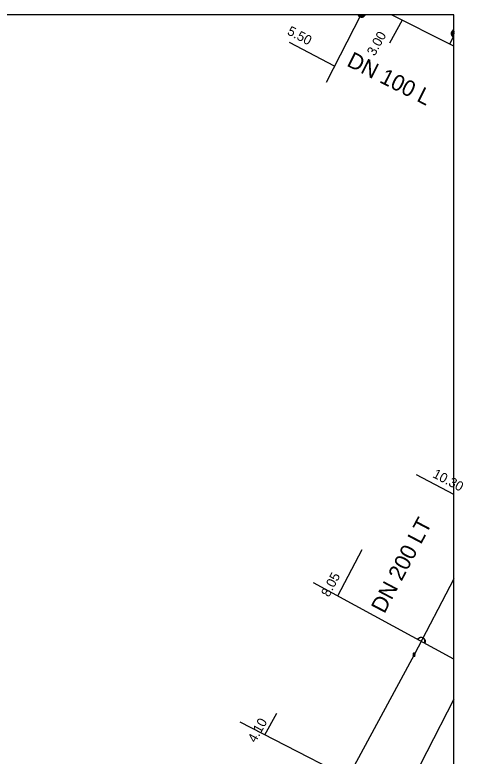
# Model space of a CAD drawing. Extents: x -820257 to -819974, y -1070894 to -1070484.
# Drawn here: x -820030.6 to -819974.5, y -1070577.4 to -1070484.4 of the extents above; entities that cross this region are included whole.
import ezdxf

# ---------------------------------------------------------------- set-up
doc = ezdxf.new("R2010")
doc.units = 0
for name, color, linetype in [('Default', 7, 'Continuous'), ('Lomový bod vodovodu', 7, 'Continuous'), ('Nepropojené křížení vodovodu', 7, 'Continuous'), ('Oměrka vodovodu', 7, 'Continuous'), ('Oměrka-text', 7, 'Continuous'), ('Přípojka vodovodu', 7, 'Continuous'), ('Přípojkový uzávěr', 7, 'Continuous'), ('Roz-řad', 7, 'Continuous'), ('Roz-řad-popis základní', 7, 'Continuous')]:
    doc.layers.add(name, color=color, linetype=linetype)

msp = doc.modelspace()

# ---------------------------------------------------------------- linework, layer by layer
at = {"layer": 'Default'}
msp.add_line((-819975.603, -1070893.932), (-819975.603, -1070484.403), dxfattribs=at)
msp.add_lwpolyline([(-819975.603, -1070484.403), (-820256.81, -1070484.403), (-820256.81, -1070893.932)], dxfattribs=at)
at = {"layer": 'Lomový bod vodovodu'}
for points in [[(-819980.638, -1070564.586), (-819980.7, -1070564.45), (-819980.5, -1070564.45), (-819980.563, -1070564.586)], [(-819980.563, -1070564.714), (-819980.5, -1070564.85), (-819980.7, -1070564.85), (-819980.638, -1070564.714)], [(-819980.578, -1070564.579), (-819980.524, -1070564.463), (-819980.678, -1070564.463), (-819980.623, -1070564.579)], [(-819980.623, -1070564.721), (-819980.678, -1070564.838), (-819980.524, -1070564.838), (-819980.578, -1070564.721)], [(-819980.632, -1070564.703), (-819980.608, -1070564.65), (-819980.632, -1070564.597)], [(-819980.618, -1070564.59), (-819980.6, -1070564.628), (-819980.583, -1070564.59)], [(-819980.583, -1070564.71), (-819980.6, -1070564.672), (-819980.618, -1070564.71)], [(-819980.568, -1070564.597), (-819980.592, -1070564.65), (-819980.568, -1070564.703)]]:
    msp.add_lwpolyline(points, dxfattribs=at)
for points in [[(-819980.638, -1070564.714), (-819980.655, -1070564.705), (-819980.665, -1070564.687), (-819980.675, -1070564.67), (-819980.675, -1070564.65), (-819980.675, -1070564.63), (-819980.665, -1070564.613), (-819980.655, -1070564.595), (-819980.638, -1070564.586)], [(-819980.632, -1070564.597), (-819980.646, -1070564.605), (-819980.654, -1070564.619), (-819980.662, -1070564.634), (-819980.662, -1070564.65), (-819980.662, -1070564.666), (-819980.654, -1070564.681), (-819980.646, -1070564.695), (-819980.632, -1070564.703)], [(-819980.623, -1070564.579), (-819980.612, -1070564.575), (-819980.6, -1070564.575), (-819980.589, -1070564.575), (-819980.578, -1070564.579)], [(-819980.578, -1070564.721), (-819980.588, -1070564.725), (-819980.6, -1070564.725), (-819980.612, -1070564.725), (-819980.623, -1070564.721)], [(-819980.583, -1070564.59), (-819980.591, -1070564.588), (-819980.6, -1070564.588), (-819980.609, -1070564.588), (-819980.618, -1070564.59)], [(-819980.618, -1070564.71), (-819980.609, -1070564.712), (-819980.6, -1070564.712), (-819980.591, -1070564.712), (-819980.583, -1070564.71)], [(-819980.568, -1070564.703), (-819980.554, -1070564.695), (-819980.546, -1070564.681), (-819980.538, -1070564.666), (-819980.538, -1070564.65), (-819980.538, -1070564.634), (-819980.546, -1070564.619), (-819980.554, -1070564.605), (-819980.568, -1070564.597)], [(-819980.563, -1070564.586), (-819980.545, -1070564.595), (-819980.535, -1070564.613), (-819980.525, -1070564.63), (-819980.525, -1070564.65), (-819980.525, -1070564.67), (-819980.535, -1070564.687), (-819980.545, -1070564.705), (-819980.563, -1070564.714)]]:
    msp.add_open_spline(points, degree=3, dxfattribs=at)
at = {"layer": 'Nepropojené křížení vodovodu'}
for points in [[(-819980.125, -1070562.743), (-819980.153, -1070562.728)], [(-819979.274, -1070563.206), (-819979.302, -1070563.191)]]:
    msp.add_lwpolyline(points, dxfattribs=at)
for points in [[(-819980.153, -1070562.728), (-819980.09, -1070562.613), (-819979.974, -1070562.539), (-819979.857, -1070562.466), (-819979.722, -1070562.467), (-819979.586, -1070562.467), (-819979.475, -1070562.528), (-819979.364, -1070562.588), (-819979.29, -1070562.702), (-819979.216, -1070562.815), (-819979.214, -1070562.953), (-819979.212, -1070563.092), (-819979.274, -1070563.206)], [(-819979.302, -1070563.191), (-819979.243, -1070563.083), (-819979.245, -1070562.954), (-819979.248, -1070562.825), (-819979.317, -1070562.718), (-819979.386, -1070562.612), (-819979.49, -1070562.555), (-819979.594, -1070562.499), (-819979.721, -1070562.498), (-819979.849, -1070562.497), (-819979.958, -1070562.566), (-819980.067, -1070562.635), (-819980.125, -1070562.743)]]:
    msp.add_open_spline(points, degree=3, dxfattribs=at)
at = {"layer": 'Oměrka vodovodu'}
for p, q in [((-819982.087, -1070485.072), (-819983.683, -1070487.954)), ((-819990.557, -1070490.842), (-819996.21, -1070487.88)), ((-819975.603, -1070544.542), (-819980.28, -1070542.08)), ((-819990.153, -1070557.282), (-819987.106, -1070551.477)), ((-819999.32, -1070574.708), (-819997.811, -1070572.003))]:
    msp.add_line(p, q, dxfattribs=at)
at = {"layer": 'Přípojka vodovodu'}
for points in [[(-819987.283, -1070484.403), (-819991.608, -1070492.908)], [(-819976.119, -1070488.078), (-819975.603, -1070487.054)], [(-819975.603, -1070522.379), (-819975.649, -1070522.355)], [(-819975.603, -1070565.205), (-819993.199, -1070555.624)], [(-819982.38, -1070583.418), (-819983.714, -1070582.732), (-820002.391, -1070573.129)]]:
    msp.add_lwpolyline(points, dxfattribs=at)
at = {"layer": 'Přípojkový uzávěr'}
for p, q in [((-819987.574, -1070484.403), (-819987.627, -1070484.403)), ((-819987.483, -1070484.403), (-819987.535, -1070484.403)), ((-819987.37, -1070484.403), (-819987.426, -1070484.403)), ((-819987.044, -1070484.403), (-819987.302, -1070484.403)), ((-819986.926, -1070484.403), (-819986.98, -1070484.403)), ((-819986.814, -1070484.403), (-819986.866, -1070484.403)), ((-819986.722, -1070484.403), (-819986.775, -1070484.403)), ((-819975.603, -1070486.313), (-819975.603, -1070486.263)), ((-819975.603, -1070486.398), (-819975.603, -1070486.35)), ((-819975.603, -1070486.495), (-819975.603, -1070486.45)), ((-819975.603, -1070486.61), (-819975.603, -1070486.544)), ((-819975.603, -1070486.8), (-819975.603, -1070486.679)), ((-819975.603, -1070486.933), (-819975.603, -1070486.868)), ((-819975.603, -1070487.027), (-819975.603, -1070486.981)), ((-819975.603, -1070487.127), (-819975.603, -1070487.079)), ((-819975.603, -1070487.213), (-819975.603, -1070487.163))]:
    msp.add_line(p, q, dxfattribs=at)
for points, degree in [([(-819987.627, -1070484.403), (-819987.613, -1070484.433), (-819987.594, -1070484.461), (-819987.517, -1070484.575), (-819987.4, -1070484.635), (-819987.284, -1070484.693), (-819987.149, -1070484.689), (-819987.013, -1070484.684), (-819986.9, -1070484.607), (-819986.787, -1070484.531), (-819986.729, -1070484.416), (-819986.725, -1070484.41), (-819986.722, -1070484.403)], 3), ([(-819986.775, -1070484.403), (-819986.828, -1070484.502), (-819986.926, -1070484.568), (-819987.028, -1070484.638), (-819987.151, -1070484.642), (-819987.274, -1070484.646), (-819987.379, -1070484.593), (-819987.485, -1070484.539), (-819987.554, -1070484.435), (-819987.565, -1070484.42), (-819987.574, -1070484.403)], 3), ([(-819987.535, -1070484.403), (-819987.53, -1070484.41), (-819987.526, -1070484.417), (-819987.461, -1070484.513), (-819987.364, -1070484.562), (-819987.266, -1070484.612), (-819987.153, -1070484.608), (-819987.039, -1070484.604), (-819986.945, -1070484.54), (-819986.862, -1070484.484), (-819986.814, -1070484.403)], 3), ([(-819986.866, -1070484.403), (-819986.935, -1070484.505), (-819987.058, -1070484.545), (-819987.205, -1070484.594), (-819987.344, -1070484.523), (-819987.431, -1070484.478), (-819987.483, -1070484.403)], 3), ([(-819987.426, -1070484.403), (-819987.385, -1070484.451), (-819987.324, -1070484.482), (-819987.203, -1070484.543), (-819987.074, -1070484.502), (-819986.983, -1070484.472), (-819986.926, -1070484.403)], 3), ([(-819986.98, -1070484.403), (-819987.025, -1070484.444), (-819987.086, -1070484.464), (-819987.2, -1070484.501), (-819987.306, -1070484.446), (-819987.342, -1070484.428), (-819987.37, -1070484.403)], 3), ([(-819987.302, -1070484.403), (-819987.295, -1070484.408), (-819987.287, -1070484.412), (-819987.195, -1070484.459), (-819987.096, -1070484.426), (-819987.068, -1070484.417), (-819987.044, -1070484.403)], 3), ([(-819975.891, -1070486.514), (-819975.948, -1070486.627), (-819975.944, -1070486.763), (-819975.941, -1070486.898), (-819975.863, -1070487.012), (-819975.786, -1070487.126), (-819975.669, -1070487.185), (-819975.637, -1070487.202), (-819975.603, -1070487.213)], 3), ([(-819975.603, -1070487.163), (-819975.626, -1070487.155), (-819975.648, -1070487.143), (-819975.754, -1070487.09), (-819975.824, -1070486.987), (-819975.894, -1070486.883), (-819975.898, -1070486.76), (-819975.901, -1070486.637), (-819975.85, -1070486.535)], 3), ([(-819975.603, -1070486.263), (-819975.667, -1070486.284), (-819975.723, -1070486.324), (-819975.835, -1070486.402), (-819975.891, -1070486.514)], 3), ([(-819975.819, -1070486.551), (-819975.866, -1070486.645), (-819975.863, -1070486.759), (-819975.86, -1070486.872), (-819975.796, -1070486.968), (-819975.731, -1070487.063), (-819975.633, -1070487.113), (-819975.618, -1070487.12), (-819975.603, -1070487.127)], 3), ([(-819975.85, -1070486.535), (-819975.798, -1070486.433), (-819975.697, -1070486.363), (-819975.652, -1070486.331), (-819975.603, -1070486.313)], 3), ([(-819975.603, -1070487.079), (-819975.608, -1070487.076), (-819975.613, -1070487.074), (-819975.752, -1070487.004), (-819975.801, -1070486.857), (-819975.85, -1070486.71), (-819975.78, -1070486.571)], 3), ([(-819975.603, -1070486.35), (-819975.642, -1070486.366), (-819975.678, -1070486.391), (-819975.771, -1070486.456), (-819975.819, -1070486.551)], 3), ([(-819975.739, -1070486.591), (-819975.8, -1070486.713), (-819975.758, -1070486.842), (-819975.717, -1070486.966), (-819975.603, -1070487.027)], 3), ([(-819975.78, -1070486.571), (-819975.719, -1070486.45), (-819975.603, -1070486.398)], 2), ([(-819975.603, -1070486.981), (-819975.688, -1070486.928), (-819975.72, -1070486.83), (-819975.758, -1070486.716), (-819975.704, -1070486.609)], 3), ([(-819975.603, -1070486.45), (-819975.691, -1070486.496), (-819975.739, -1070486.591)], 2), ([(-819975.668, -1070486.627), (-819975.715, -1070486.72), (-819975.682, -1070486.818), (-819975.658, -1070486.889), (-819975.603, -1070486.933)], 3), ([(-819975.704, -1070486.609), (-819975.667, -1070486.536), (-819975.603, -1070486.495)], 2), ([(-819975.603, -1070486.544), (-819975.643, -1070486.576), (-819975.668, -1070486.627)], 2), ([(-819975.603, -1070486.868), (-819975.626, -1070486.84), (-819975.638, -1070486.802), (-819975.665, -1070486.723), (-819975.627, -1070486.647)], 3), ([(-819975.627, -1070486.647), (-819975.616, -1070486.627), (-819975.603, -1070486.61)], 2), ([(-819975.603, -1070486.679), (-819975.625, -1070486.734), (-819975.606, -1070486.792), (-819975.604, -1070486.796), (-819975.603, -1070486.8)], 3)]:
    msp.add_open_spline(points, degree=degree, dxfattribs=at)
at = {"layer": 'Roz-řad'}
for points in [[(-819975.603, -1070488.338), (-819976.119, -1070488.078), (-819983.415, -1070484.403)], [(-819975.603, -1070555.156), (-819980.6, -1070564.65), (-819996.48, -1070594.05), (-820003.11, -1070606.6), (-820007.73, -1070614.37), (-820021.61, -1070627.51)], [(-819975.603, -1070570.213), (-819982.38, -1070583.418), (-819988.683, -1070595.88)]]:
    msp.add_lwpolyline(points, dxfattribs=at)

# ---------------------------------------------------------------- texts
at = {"layer": 'Oměrka-text'}
for s, rotation, p in [(' 5.50', 332.34686, (-819996.989, -1070486.601)), (' 3.00', 61.03015, (-819985.761, -1070490.037)), ('10.30', 332.23892, (-819978.374, -1070542.349)), (' 8.05', 62.30538, (-819991.475, -1070557.9)), (' 4.10', 60.84479, (-820000.694, -1070576.155))]:
    msp.add_text(s, height=1.2, rotation=rotation, dxfattribs=at).set_placement(p)
at = {"layer": 'Roz-řad-popis základní'}
for s, rotation, p in [('DN 100 L', 333.26623, (-819989.163, -1070490.745)), ('DN 200 LT', 62.23892, (-819984.327, -1070559.597))]:
    msp.add_text(s, height=2, rotation=rotation, dxfattribs=at).set_placement(p)

doc.saveas('drawing.dxf')
